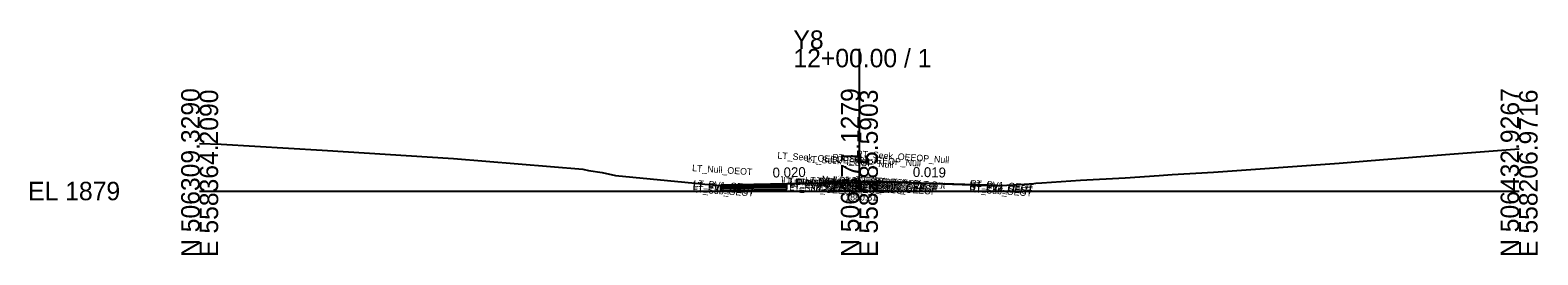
# Model space of a CAD drawing. Extents: x -26 to 203, y -10 to 8070.
# Drawn here: x -25.7 to 202.8, y 1990.3 to 2024.4 of the extents above; entities that cross this region are included whole.
import ezdxf

# ---------------------------------------------------------------- set-up
doc = ezdxf.new("R2010")
doc.units = 0
for name, color, linetype in [('Default', 7, 'Continuous'), ('Exist Cross Section Cell', 7, 'Continuous'), ('Exist XS Center Line Elevation Label', 7, 'Continuous'), ('Exist XS Ground Line', 7, 'Continuous'), ('Prop CMT Pvmt Course 1', 7, 'Continuous'), ('Prop CMT Pvmt Course 2', 7, 'Continuous'), ('Prop CMT Pvmt Course 3', 7, 'Continuous'), ('Prop CMT Pvmt Surface', 7, 'Continuous'), ('Prop CMT Subgrade Earthwork', 7, 'Continuous'), ('Prop XS Earthwork Shape', 7, 'Continuous'), ('Prop XS SE Text', 7, 'Continuous'), ('Typical Text Grade Point CELL', 7, 'Continuous')]:
    doc.layers.add(name, color=color, linetype=linetype)

msp = doc.modelspace()

# ---------------------------------------------------------------- linework, layer by layer
at = {"layer": 'Exist Cross Section Cell'}
for p, q in [((100, 2000), (100, 2021.58)), ((0, 2000), (100, 2000)), ((100, 2000), (200, 2000))]:
    msp.add_line(p, q, dxfattribs=at)
at = {"layer": 'Exist XS Ground Line'}
for p, q in [((0, 2007.19), (3.25, 2007.12)), ((3.25, 2007.12), (18.55, 2006.22)), ((18.55, 2006.22), (38.49, 2004.96)), ((38.49, 2004.96), (58.09, 2003.33)), ((153.67, 2002.88), (172.71, 2004.24)), ((172.71, 2004.24), (176.95, 2004.58)), ((176.95, 2004.58), (188.82, 2005.52)), ((188.82, 2005.52), (200, 2006.42)), ((58.09, 2003.33), (58.92, 2003.1)), ((58.92, 2003.1), (60.99, 2002.8)), ((60.99, 2002.8), (63.02, 2002.36)), ((63.02, 2002.36), (76.18, 2001.1)), ((133.54, 2001.66), (140.28, 2002.01)), ((140.28, 2002.01), (145.44, 2002.38)), ((145.44, 2002.38), (147.39, 2002.5)), ((147.39, 2002.5), (153.67, 2002.88)), ((76.18, 2001.1), (76.55, 2001.04)), ((76.55, 2001.04), (77.19, 2000.99)), ((77.19, 2000.99), (77.79, 2000.94)), ((77.79, 2000.94), (78.91, 2000.83)), ((78.91, 2000.83), (88.28, 2001.07)), ((88.28, 2001.07), (100, 2001.31)), ((100, 2001.31), (100.8, 2001.32)), ((100.8, 2001.32), (100.87, 2001.43)), ((100.87, 2001.43), (103.94, 2001.4)), ((103.94, 2001.4), (115.59, 2001.01)), ((115.59, 2001.01), (120.67, 2000.78)), ((120.67, 2000.78), (121.39, 2000.83)), ((121.39, 2000.83), (124.27, 2001.01)), ((124.27, 2001.01), (126.43, 2001.16)), ((126.43, 2001.16), (126.74, 2001.18)), ((126.74, 2001.18), (127.68, 2001.24)), ((127.68, 2001.24), (133.54, 2001.66))]:
    msp.add_line(p, q, dxfattribs=at)
at = {"layer": 'Prop CMT Pvmt Course 1'}
for points in [[(100, 2001.31), (98, 2001.27), (97.99, 2001.27), (94.01, 2001.19), (94, 2001.19), (79, 2000.89)], [(79, 2000.89), (79, 2000.64)], [(79, 2000.64), (89, 2000.84)], [(100, 2001.31), (102, 2001.42), (102.01, 2001.42), (105.99, 2001.33), (106, 2001.33), (121, 2000.9)], [(121, 2000.9), (121, 2000.77)]]:
    msp.add_lwpolyline(points, dxfattribs=at)
at = {"layer": 'Prop CMT Pvmt Course 2'}
for points in [[(89, 2000.84), (79, 2000.64)], [(79, 2000.64), (79, 2000.39)], [(79, 2000.39), (89, 2000.59)]]:
    msp.add_lwpolyline(points, dxfattribs=at)
at = {"layer": 'Prop CMT Pvmt Course 3'}
for points in [[(89, 2000.59), (79, 2000.39)], [(79, 2000.39), (79, 2000.01)], [(79, 2000.01), (89, 2000.21)]]:
    msp.add_lwpolyline(points, dxfattribs=at)
at = {"layer": 'Prop CMT Pvmt Surface'}
for points in [[(100, 2001.31), (98, 2001.27), (97.99, 2001.27), (94.01, 2001.19), (94, 2001.19), (79, 2000.89)], [(100, 2001.31), (102, 2001.42), (102.01, 2001.42), (105.99, 2001.33), (106, 2001.33), (121, 2000.9)]]:
    msp.add_lwpolyline(points, dxfattribs=at)
at = {"layer": 'Prop CMT Subgrade Earthwork'}
msp.add_line((121, 2000.77), (121, 2000.9), dxfattribs=at)
for points in [[(79, 2000.01), (79, 2000.83)], [(89, 2000.21), (79, 2000.01)], [(89, 2000.21), (89, 2001.09)]]:
    msp.add_lwpolyline(points, dxfattribs=at)
at = {"layer": 'Prop XS Earthwork Shape'}
for points in [[(100.8, 2001.32), (102, 2001.42), (100.87, 2001.43)], [(102, 2001.42), (105.99, 2001.33), (107.09, 2001.3), (103.94, 2001.4)]]:
    msp.add_lwpolyline(points, close=True, dxfattribs=at)

# ---------------------------------------------------------------- texts
at = {"layer": 'Default'}
msp.add_text('-', height=0.0001, dxfattribs=at).set_placement((0, 2000))
at = {"layer": 'Exist Cross Section Cell'}
for s, p in [('Y8', (90, 2021.58)), ('12+00.00 / 1', (90, 2018.78)), ('EL 1879', (-26, 1998.6))]:
    msp.add_text(s, height=2.8, dxfattribs=at).set_placement(p)
for s, p in [('N 506309.3290', (0, 1990)), ('E 558364.2090', (2.8, 1990)), ('N 506371.1279', (100, 1990)), ('E 558285.5903', (102.8, 1990)), ('N 506432.9267', (200, 1990)), ('E 558206.9716', (202.8, 1990))]:
    msp.add_text(s, height=2.8, rotation=90, dxfattribs=at).set_placement(p)
at = {"layer": 'Exist XS Center Line Elevation Label'}
msp.add_text('1880.31', height=1, dxfattribs=at).set_placement((97.86, 1998.56))
at = {"layer": 'Prop XS SE Text'}
for s, rotation, p in [('0.020', 1.1454, (86.86, 2002.04)), ('0.019', 358.8903, (108.09, 2002.15))]:
    msp.add_text(s, height=1.5, rotation=rotation, dxfattribs=at).set_placement(p)
at = {"layer": 'Typical Text Grade Point CELL'}
for s, p in [('LT_Seek_OEEOP_Null', (87.55, 2004.92)), ('LT_Seek_IEEOP_Null', (91.93, 2004.4)), ('RT_Seek_IEEOP_Null', (95.87, 2004.65)), ('RT_Seek_OEEOP_Null', (99.49, 2005.18)), ('LT_Null_OEOT', (74.62, 2003.03)), ('LT_PV_Sub_Tie_Out', (88.14, 2001.09)), ('LT_Null OEEOP Test', (88.4, 2001.12)), ('LT_Null IEEOP Test', (91.78, 2001.16)), ('LT_PV_Sub_Tie_In', (92.76, 2001.13)), ('Null RT Pvmt Slope', (94.26, 2001.34)), ('Null LT Pvmt Slope', (94.32, 2001.2)), ('PV1_Overlay_Null', (94.75, 2001.05)), ('LT_Pvmt In', (94.84, 2000.99)), ('RT_PV_Sub_Tie_In', (96.7, 2001.29)), ('RT_Null IEEOP Test', (96.72, 2001.32)), ('PV1_PGL', (97.44, 2000.98)), ('RT_Pvmt In', (98.8, 2001.14)), ('RT_Null OEEOP Test', (99.34, 2001.27)), ('RT_PV_Sub_Tie_Out', (100.09, 2001.24)), ('RT_Pvmt Out', (102.17, 2001.09)), ('LT_PV2_OEOT', (74.72, 2000.43)), ('LT_PV3_OEOT', (74.72, 2000.18)), ('LT_Sub_OEOT', (74.74, 1999.81)), ('LT_PV1_OEOT', (74.84, 2000.68)), ('LT_PV2_OEEOP', (89.37, 2000.76)), ('LT_PV3_OEEOP', (89.37, 2000.51)), ('LT_Sub_OEEOP', (89.39, 2000.13)), ('LT_PV1_OEEOP', (89.49, 2000.88)), ('LT_Pvmt Out', (90.25, 2000.95)), ('LT_PV2_IEEOP', (93.75, 2000.81)), ('LT_PV3_IEEOP', (93.75, 2000.56)), ('LT_Sub_IEEOP', (93.77, 2000.19)), ('LT_PV1_IEEOP', (93.87, 2000.93)), ('Sub_PGL', (97.34, 2000.12)), ('PV2_PGL', (97.32, 2000.74)), ('PV3_PGL', (97.32, 2000.49)), ('RT_PV2_IEEOP', (97.69, 2000.82)), ('RT_PV3_IEEOP', (97.69, 2000.57)), ('RT_Sub_IEEOP', (97.71, 2000.19)), ('RT_PV1_IEEOP', (97.81, 2000.93)), ('CL', (99.2, 2000.78)), ('RT_PV2_OEEOP', (101.31, 2000.77)), ('RT_PV3_OEEOP', (101.31, 2000.52)), ('RT_Sub_OEEOP', (101.33, 2000.14)), ('RT_PV1_OEEOP', (101.43, 2000.88)), ('RT_PV2_OEOT', (116.66, 2000.45)), ('RT_PV3_OEOT', (116.66, 2000.2)), ('RT_Sub_OEOT', (116.69, 1999.83)), ('RT_PV1_OEOT', (116.78, 2000.69))]:
    msp.add_text(s, height=1, rotation=356, dxfattribs=at).set_placement(p)

doc.saveas('drawing.dxf')
